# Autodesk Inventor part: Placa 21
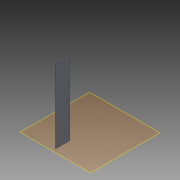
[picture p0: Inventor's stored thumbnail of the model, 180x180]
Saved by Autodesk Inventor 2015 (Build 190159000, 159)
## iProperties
Created: 2015-04
Part Number: Placa 21
Material: Generic
Document SubType Name: Modeling
Designer: suporte
Density: 1 g/cm^3
Appearance: Default
Author: suporte
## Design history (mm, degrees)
workplane "Work Plane1"
sketch "Sketch1"
  geometry: L1 (-87.5, -500)-(-87.5, -900) reference; L2 (-87.5, -500)-(-87.5, -487.5) reference; L3 (-100, -887.5)-(-87.5, -887.5); L4 (-87.5, -887.5)-(-87.5, -487.5); L5 (-87.5, -487.5)-(-100, -487.5); L6 (-100, -487.5)-(-100, -887.5); 1 further point
  constraints: 8 end point, 2 parallel, 1 horizontal, 1 perpendicular, 1 other
extrude "Extrusion1" new body sketch "Sketch1" distance "d0" = 2100; taper "d1" = 0 deg
body "Solid1"
node "Reference1"
node "Reference2"
